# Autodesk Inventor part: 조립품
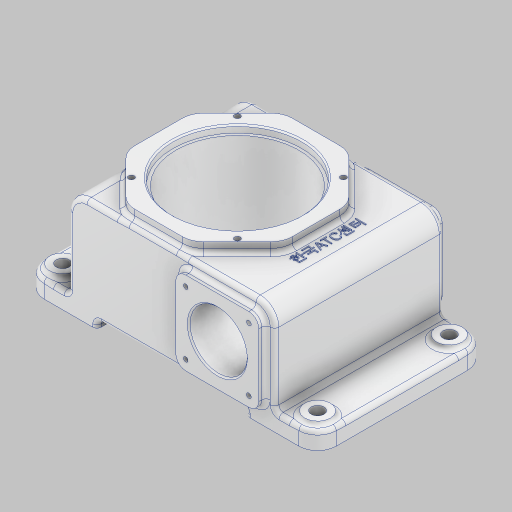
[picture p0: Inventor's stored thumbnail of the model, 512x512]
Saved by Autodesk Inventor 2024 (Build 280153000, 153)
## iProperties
Created: 2026-02
Part Number: 조립품
Material: 알루미늄 6061
Document SubType Name: Modeling
Designer: 2-10
Density: 2.7 g/cm^3
Appearance: 알루미늄 - 평지
Mass: 2338.38 g
Surface Area: 1210.62 cm^2
Volume: 866.066 cm^3
Author: 2-10
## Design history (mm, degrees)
sketch "스케치1"
  geometry: L1 (-72, -35)-(72, -35); L2 (72, -35)-(72, 35); L3 (72, 35)-(-72, 35); L4 (-72, 35)-(-72, -35); L5 (-72, -35)-(72, 35); L6 (72, -35)-(-72, 35); L7 (-102, -28)-(-52, -28); L8 (-52, -28)-(-52, -40); L9 (-52, -40)-(-102, -40); L10 (-102, -40)-(-102, -28); L11 (-102, -28)-(-52, -40); L12 (-52, -28)-(-102, -40); L13 (52, -28)-(102, -28); L14 (102, -28)-(102, -40); L15 (102, -40)-(52, -40); L16 (52, -40)-(52, -28); L17 (52, -28)-(102, -40); L18 (102, -28)-(52, -40); 6 further points
  constraints: 36 end point, 8 midpoint, 6 parallel, 3 horizontal, 3 perpendicular, 2 equal length, 1 coincident
  dimensions: "d0" = 144 distance of L3.end L2.end; "d1" = 70 distance of L2.end L1.end; "d3" = 50 distance between parallel lines of L8 L10; "d6" = 204 distance between parallel lines of L14 L10; "d7" = 30 distance between parallel lines of L14 L2; "d42" = 5 distance between parallel lines of L1 L15; "d43" = 12 distance between parallel lines of L13 L15; "d44" = 5 distance between parallel lines of L1 L9
extrude "돌출1" new body sketch "스케치1" stored distance "d8" = 118; taper "d9" = 0 deg
extrude "돌출2" join sketch "스케치1" stored distance "d10" = 118; taper "d11" = 0 deg
sketch "스케치2"
  geometry: L1 (52, -40)-(102, -40) reference; L2 (102, -28)-(72, -28) reference; L3 (15, -29)-(59, -29); L4 (66, -22)-(66, 22); L5 (59, 29)-(15, 29); L6 (8, 22)-(8, -22); L7 (8, -29)-(66, 29); L8 (66, -29)-(8, 29); L9 (102, -40)-(102, -28) reference; A1 r 7 centre (15, 22) between (15, 29) and (8, 22); A2 r 7 centre (15, -22) between (8, -22) and (15, -29); A3 r 7 centre (59, -22) between (59, -29) and (66, -22); A4 r 7 centre (59, 22) between (66, 22) and (59, 29); 4 further points
  constraints: 12 end point, 8 point on circle, 8 point on line, 8 tangent, 4 centre point, 4 midpoint, 3 equal radius, 2 parallel, 1 horizontal, 1 perpendicular
  dimensions: "d12" = 58 distance of L8.end L7.end; "d13" = 58 distance of L7.end L8.start; "d14" = 40 distance from line of point (37, 0) L1; "d16" = 7 radius of A1; "d137" = 65 distance from line of point (37, 29) L9
extrude "돌출3" join sketch "스케치2" distance "d17" = 5; taper "d18" = 0 deg
sketch "스케치3"
  geometry: L1 (8.393, 86.175)-(31.825, 109.607); L2 (42.431, 114)-(75.569, 114); L3 (86.175, 109.607)-(109.607, 86.175); L4 (114, 75.569)-(114, 42.431); L5 (109.607, 31.825)-(86.175, 8.393); L6 (75.569, 4)-(42.431, 4); L7 (31.825, 8.393)-(8.393, 31.825); L8 (4, 42.431)-(4, 75.569); L9 (131, 123)-(87, 123) reference; L10 (131, -5)-(87, -5) reference; L11 (-30, 118)-(-30, 0) reference; A1 r 15 centre (42.431, 19) between (31.825, 8.393) and (42.431, 4); A2 r 15 centre (19, 42.431) between (4, 42.431) and (8.393, 31.825); A3 r 15 centre (19, 75.569) between (8.393, 86.175) and (4, 75.569); A4 r 15 centre (42.431, 99) between (42.431, 114) and (31.825, 109.607); A5 r 15 centre (75.569, 99) between (86.175, 109.607) and (75.569, 114); A6 r 15 centre (99, 75.569) between (114, 75.569) and (109.607, 86.175); A7 r 15 centre (99, 42.431) between (109.607, 31.825) and (114, 42.431); A8 r 15 centre (75.569, 19) between (75.569, 4) and (86.175, 8.393); 13 further points
  constraints: 16 end point, 16 point on circle, 16 point on line, 16 tangent, 8 centre point, 7 equal radius, 4 midpoint, 1 horizontal alignment, 1 vertical, 17 other
  dimensions: "d31" = 15 radius of A1; "d138" = 50 horizontal distance of point (59, 59) point (109, -5); "d141" = 110 distance between parallel lines of L2 L6
extrude "돌출4" join sketch "스케치3" distance "d32" = 7; taper "d33" = 0 deg
sketch "스케치4"
  geometry: L1 (59, 29)-(15, 29) reference; L2 (15, -29)-(59, -29) reference; L3 (8, 22)-(8, -22) reference; L4 (59, 29)-(15, 29) reference; L5 (66, -22)-(66, 22) reference; L6 (-13, 76.49)-(-13, -76.49); L7 (-63.607, 42)-(-40.175, 42) reference; L8 (-29.569, 42)-(-40.175, 42) reference; L9 (-29.569, 42)-(3.569, 42) reference; L10 (14.175, 42)-(3.569, 42) reference; L11 (14.175, 42)-(37.607, 42) reference; L12 (42, 42)-(37.607, 42) reference; L13 (-63.607, 42)-(-68, 42) reference; L14 (-58, 42)-(-58, 37); L15 (-58, 37)-(-56, 37); L16 (-56, 37)-(-56, -24); L17 (-56, -24)-(-13, -24); A1 r 7 centre (59, -22) between (59, -29) and (66, -22) reference; A2 r 7 centre (15, -22) between (8, -22) and (15, -29) reference; A3 r 7 centre (15, 22) between (15, 29) and (8, 22) reference; A4 r 7 centre (59, 22) between (66, 22) and (59, 29) reference; 5 further points
  constraints: 10 end point, 3 perpendicular, 2 midpoint, 2 point on line, 2 vertical, 1 horizontal alignment
  dimensions: "d34" = 50 distance from line of L6 point (37, -29); "d35" = 90 diameter of L14 L6; "d36" = 86 diameter of L16 L6; "d37" = 5 distance between parallel lines of L15 L7; "d38" = 66 distance between parallel lines of L17 L7
revolve "회전1" sketch "스케치4" stored, may be unused: angle "d45" = 90 deg
sketch "스케치5"
  geometry: L1 (30, -24)-(-56, -24) reference; L2 (-13, 15.405)-(-13, -63.405); L3 (-58, 42)-(32, 42) reference; L4 (-13, -18)-(12, -18); L5 (12, -18)-(18, -24); 2 further points
  constraints: 6 end point, 2 midpoint, 2 point on line, 1 horizontal, 1 vertical
  dimensions: "d48" = 6 distance between parallel lines of L4 L1; "d49" = 45 deg angle of L2 L5; "d50" = 50 diameter of L4.end L2
revolve "회전2" sketch "스케치5" stored, may be unused: angle "d51" = 90 deg
sketch "스케치6"
  geometry: L1 (-13, 36)-(-13, -72); L2 (-38, -18)-(12, -18) reference; L3 (-33, -18)-(-33, -27.5); L4 (-31.5, -29)-(-13, -29); A1 r 1.5 centre (-31.5, -27.5) between (-33, -27.5) and (-31.5, -29); 3 further points
  constraints: 6 end point, 4 point on line, 2 midpoint, 2 point on circle, 2 tangent, 2 vertical, 1 centre point, 1 perpendicular
  dimensions: "d52" = 40 diameter of L3 L1; "d53" = 11 distance between parallel lines of L2 L4; "d55" = 1.5 radius of A1
revolve "회전3" sketch "스케치6" stored, may be unused: angle "d54" = 90 deg
sketch "스케치7"
  geometry: L1 (59, 29)-(15, 29) reference; L2 (8, 22)-(8, -22) reference; C1 r 20 at (37, 0); 3 further points
  constraints: 2 midpoint, 1 centre point, 1 horizontal alignment, 1 vertical alignment
  dimensions: "d56" = 40 diameter of C1
extrude "돌출5" cut sketch "스케치7" extent not by distance; stored distance "d57" = 0; taper "d58" = 0 deg
fillet "모깎기19" dims "d135" = 13
fillet "모깎기1" dims "d59" = 13
fillet "모깎기3" dims "d61" = 3
sketch "스케치10"
  geometry: L1 (0, 7)-(44, 7); L2 (44, 7)-(44, 51); L3 (44, 51)-(0, 51); L4 (0, 51)-(0, 7); L5 (0, 7)-(44, 51); L6 (44, 7)-(0, 51); C1 r 20 at (22, 29) reference; 5 further points
  constraints: 12 end point, 4 coincident, 2 midpoint, 2 parallel, 1 horizontal, 1 perpendicular
  dimensions: "d88" = 44 distance of L3.end L2.end; "d89" = 44 distance of L2.end L1.end
hole "구멍2" sketch "스케치10" at (0, 51), (44, 51), (0, 7), (44, 7) diameter "d81" = 3.242; stored, may be unused: countersink angle "d85" = 90 deg, drill point angle "d87" = 118 deg; dims "d82" = 8, "d83" = 4, "d84" = 2, "d86" = 10
sketch "스케치11"
  geometry: L1 (96, 22)-(22, 22); L2 (22, 22)-(22, 96); L3 (22, 96)-(96, 96); L4 (96, 96)-(96, 22); L5 (96, 22)-(22, 96); L6 (22, 22)-(96, 96); C1 r 45 at (59, 59) reference; 5 further points
  constraints: 12 end point, 4 coincident, 2 midpoint, 2 parallel, 1 horizontal, 1 perpendicular
  dimensions: "d97" = 74 distance of L2.end L3.end; "d98" = 74 distance of L1.end L2.end
hole "구멍3" sketch "스케치11" at (22, 22), (22, 96), (96, 22), (96, 96) diameter "d90" = 4.134; stored, may be unused: countersink angle "d94" = 90 deg, drill point angle "d96" = 118 deg; dims "d91" = 10, "d92" = 4, "d93" = 2, "d95" = 12
sketch "스케치12"
  geometry: C1 r 9 at (13, 92); C2 r 9 at (13, 0); C3 r 9 at (191, 92); C4 r 9 at (191, 0); A1 r 13 centre (13, 92) between (13, 105) and (0, 92) reference; A2 r 13 centre (13, 0) between (0, 0) and (13, -13) reference; A3 r 13 centre (191, 92) between (204, 92) and (191, 105) reference; A4 r 13 centre (191, 0) between (191, -13) and (204, 0) reference; 1 further point
  constraints: 4 centre point, 4 concentric
  dimensions: "d99" = 18 diameter of C1; "d100" = 18 diameter of C2; "d101" = 18 diameter of C4; "d102" = 18 diameter of C3
extrude "돌출7" join sketch "스케치12" distance "d103" = 3; taper "d104" = 0 deg
fillet "모깎기5" dims "d105" = 3
fillet "모깎기7" dims "d107" = 3
fillet "모깎기8" dims "d108" = 3
fillet "모깎기11" dims "d111" = 3
chamfer "모따기1" distance "d114" = 1; stored, may be unused: second distance "d115" = 2, angle "d116" = 45 deg
fillet "모깎기14" dims "d117" = 3
chamfer "모따기2" distance "d118" = 1; stored, may be unused: second distance "d119" = 2, angle "d120" = 45 deg
sketch "스케치13"
  geometry: C1 r 9 at (0, 0) reference; C2 r 9 at (0, 92) reference; C3 r 9 at (-178, 0) reference; C4 r 9 at (-178, 92) reference; 5 further points
  constraints: 4 coincident
hole "구멍4" sketch "스케치13" at (0, 0), (0, 92), (-178, 0), (-178, 92) diameter "d121" = 9; stored, may be unused: countersink angle "d125" = 90 deg, drill point angle "d127" = 0 deg; dims "d122" = 10, "d123" = 4, "d124" = 2, "d126" = 12
node "작업 평면3"
sketch "스케치14"
  geometry: C1 r 18.5 at (-58, 16.569) reference; 2 further points
  constraints: 1 horizontal alignment, 1 other
  dimensions: "d128" = 65 distance of C1.centre point (7, 16.569)
feature "엠보싱1" dims "d0" = 144, "d1" = 70, "d3" = 50, "d6" = 204, "d7" = 30, "d42" = 5, "d43" = 12, "d44" = 5, "d132" = 0.5, "d133" = 0
fillet "모깎기20" dims "d136" = 3
fillet "모깎기21" dims "d140" = 3
node "솔리드1"
mirror "미러1"
mirror "미러2"
node "투영된 루프1"
feature "A9D066F2-1C7D-4E18-AEED-F7BC21143FA4" dims "d81" = 3.242, "d82" = 8, "d83" = 4, "d84" = 2, "d85" = 90 deg, "d86" = 10, "d87" = 118 deg
